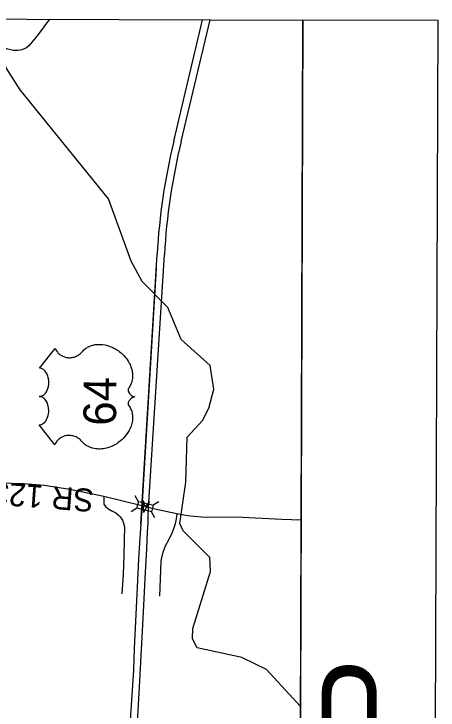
# Model space of a CAD drawing. Extents: x 2364794 to 2387902, y 795230 to 810426.
# Drawn here: x 2366848 to 2367318, y 801786 to 802558 of the extents above; entities that cross this region are included whole.
import ezdxf

# ---------------------------------------------------------------- set-up
doc = ezdxf.new("R2010")
doc.units = 0
for name, color, linetype in [('Default', 7, 'Continuous'), ('Old_Level_10', 7, 'Continuous'), ('Plot Label CELL', 7, 'Continuous'), ('Plot Shape CELL', 7, 'Continuous'), ('User Information Notes CELL', 7, 'Continuous')]:
    doc.layers.add(name, color=color, linetype=linetype)

msp = doc.modelspace()

# ---------------------------------------------------------------- linework, layer by layer
at = {"layer": 'Default'}
for p, q in [((2367318.28, 802550.69), (2367168.28, 802551.22)), ((2367310.68, 800398.89), (2367318.28, 802550.69)), ((2366937.8, 802191.08), (2366938.87, 802191.23)), ((2366938.87, 802191.23), (2366940.97, 802191.39)), ((2366940.97, 802191.39), (2366943.51, 802191.39)), ((2366943.51, 802191.39), (2366945.93, 802191.19)), ((2366945.93, 802191.19), (2366948.74, 802190.72)), ((2366875.76, 802165), (2366893.34, 802186.91)), ((2366893.34, 802186.91), (2366893.54, 802186.39)), ((2366893.54, 802186.39), (2366894.12, 802185.19)), ((2366894.12, 802185.19), (2366894.67, 802184.24)), ((2366894.67, 802184.24), (2366895.73, 802182.73)), ((2366922.49, 802182.24), (2366923.64, 802183.6)), ((2366923.64, 802183.6), (2366924.29, 802184.33)), ((2366924.29, 802184.33), (2366925.13, 802185.17)), ((2366925.13, 802185.17), (2366926.74, 802186.54)), ((2366926.74, 802186.54), (2366927.49, 802187.09)), ((2366927.49, 802187.09), (2366928.34, 802187.65)), ((2366928.34, 802187.65), (2366929.21, 802188.17)), ((2366929.21, 802188.17), (2366930.15, 802188.69)), ((2366930.15, 802188.69), (2366930.96, 802189.1)), ((2366930.96, 802189.1), (2366932.85, 802189.86)), ((2366932.85, 802189.86), (2366934.68, 802190.42)), ((2366934.68, 802190.42), (2366935.64, 802190.68)), ((2366935.64, 802190.68), (2366937.8, 802191.08)), ((2366948.74, 802190.72), (2366950.43, 802190.34)), ((2366950.43, 802190.34), (2366952.39, 802189.75)), ((2366952.39, 802189.75), (2366954.09, 802189.19)), ((2366954.09, 802189.19), (2366956.59, 802188.18)), ((2366956.59, 802188.18), (2366958.4, 802187.28)), ((2366958.4, 802187.28), (2366960.53, 802186.12)), ((2366960.53, 802186.12), (2366961.81, 802185.32)), ((2366961.81, 802185.32), (2366963.18, 802184.4)), ((2366963.18, 802184.4), (2366964.76, 802183.24)), ((2366895.73, 802182.73), (2366896.31, 802182.08)), ((2366896.31, 802182.08), (2366896.92, 802181.43)), ((2366896.92, 802181.43), (2366897.57, 802180.83)), ((2366897.57, 802180.83), (2366898.18, 802180.3)), ((2366898.18, 802180.3), (2366899.06, 802179.66)), ((2366899.06, 802179.66), (2366899.94, 802179.09)), ((2366899.94, 802179.09), (2366900.91, 802178.52)), ((2366900.91, 802178.52), (2366901.75, 802178.11)), ((2366901.75, 802178.11), (2366903.52, 802177.43)), ((2366903.52, 802177.43), (2366904.63, 802177.1)), ((2366904.63, 802177.1), (2366905.58, 802176.89)), ((2366905.58, 802176.89), (2366907.54, 802176.63)), ((2366907.54, 802176.63), (2366908.47, 802176.56)), ((2366908.47, 802176.56), (2366909.39, 802176.55)), ((2366909.39, 802176.55), (2366910.37, 802176.6)), ((2366910.37, 802176.6), (2366911.3, 802176.69)), ((2366911.3, 802176.69), (2366912.28, 802176.86)), ((2366912.28, 802176.86), (2366913.13, 802177.01)), ((2366913.13, 802177.01), (2366914.19, 802177.28)), ((2366914.19, 802177.28), (2366915.41, 802177.66)), ((2366915.41, 802177.66), (2366916.59, 802178.14)), ((2366916.59, 802178.14), (2366918.5, 802179.14)), ((2366918.5, 802179.14), (2366920.46, 802180.42)), ((2366920.46, 802180.42), (2366921.55, 802181.34)), ((2366921.55, 802181.34), (2366922.49, 802182.24)), ((2366964.76, 802183.24), (2366966.45, 802181.88)), ((2366966.45, 802181.88), (2366968.22, 802180.25)), ((2366968.22, 802180.25), (2366969.53, 802178.94)), ((2366969.53, 802178.94), (2366971.05, 802177.22)), ((2366971.05, 802177.22), (2366971.91, 802176.18)), ((2366971.91, 802176.18), (2366973.02, 802174.69)), ((2366973.02, 802174.69), (2366974.36, 802172.67)), ((2366974.36, 802172.67), (2366975.51, 802170.66)), ((2366975.51, 802170.66), (2366976.37, 802168.96)), ((2366976.37, 802168.96), (2366977.02, 802167.45)), ((2366876.41, 802164.97), (2366875.76, 802165)), ((2366877.18, 802164.87), (2366876.41, 802164.97)), ((2366878.06, 802164.65), (2366877.18, 802164.87)), ((2366878.89, 802164.3), (2366878.06, 802164.65)), ((2366879.68, 802163.92), (2366878.89, 802164.3)), ((2366880.45, 802163.38), (2366879.68, 802163.92)), ((2366881.5, 802162.47), (2366880.45, 802163.38)), ((2366882.37, 802161.51), (2366881.5, 802162.47)), ((2366883.02, 802160.7), (2366882.37, 802161.51)), ((2366883.71, 802159.59), (2366883.02, 802160.7)), ((2366977.02, 802167.45), (2366977.75, 802165.5)), ((2366977.75, 802165.5), (2366978.63, 802162.26)), ((2366978.63, 802162.26), (2366978.88, 802161.08)), ((2366978.88, 802161.08), (2366979.08, 802159.67)), ((2366884.41, 802158.23), (2366883.71, 802159.59)), ((2366884.87, 802157.18), (2366884.41, 802158.23)), ((2366885.29, 802155.98), (2366884.87, 802157.18)), ((2366885.64, 802154.66), (2366885.29, 802155.98)), ((2366885.85, 802153.66), (2366885.64, 802154.66)), ((2366886.06, 802152.41), (2366885.85, 802153.66)), ((2366979.14, 802153.68), (2366978.9, 802152.07)), ((2366979.08, 802159.67), (2366979.21, 802158.36)), ((2366979.27, 802155.38), (2366979.14, 802153.68)), ((2366979.21, 802158.36), (2366979.28, 802157.09)), ((2366979.28, 802157.09), (2366979.27, 802155.38)), ((2366885.76, 802144.51), (2366885.95, 802145.65)), ((2366885.95, 802145.65), (2366886.13, 802146.82)), ((2366886.18, 802151.28), (2366886.06, 802152.41)), ((2366886.13, 802146.82), (2366886.22, 802148.01)), ((2366886.24, 802150.18), (2366886.18, 802151.28)), ((2366886.22, 802148.01), (2366886.25, 802148.98)), ((2366886.25, 802148.98), (2366886.24, 802150.18)), ((2366976.59, 802145.45), (2366974.87, 802142.74)), ((2366977.39, 802147.06), (2366976.59, 802145.45)), ((2366978.02, 802148.65), (2366977.39, 802147.06)), ((2366978.54, 802150.4), (2366978.02, 802148.65)), ((2366978.9, 802152.07), (2366978.54, 802150.4)), ((2366882.07, 802136.72), (2366882.52, 802137.27)), ((2366882.52, 802137.27), (2366883.55, 802138.76)), ((2366883.55, 802138.76), (2366884.44, 802140.5)), ((2366884.44, 802140.5), (2366884.82, 802141.36)), ((2366884.82, 802141.36), (2366885.14, 802142.24)), ((2366885.14, 802142.24), (2366885.48, 802143.35)), ((2366885.48, 802143.35), (2366885.76, 802144.51)), ((2366974.33, 802141.52), (2366974.27, 802140.47)), ((2366974.27, 802140.47), (2366974.48, 802139.48)), ((2366974.45, 802141.96), (2366974.33, 802141.52)), ((2366974.87, 802142.74), (2366974.45, 802141.96)), ((2366974.48, 802139.48), (2366974.88, 802138.46)), ((2366974.88, 802138.46), (2366975.2, 802137.85)), ((2366975.2, 802137.85), (2366975.73, 802137.04)), ((2366875.67, 802133.55), (2366876.69, 802133.63)), ((2366876.89, 802133.46), (2366875.67, 802133.55)), ((2366876.69, 802133.63), (2366877.33, 802133.73)), ((2366877.47, 802133.33), (2366876.89, 802133.46)), ((2366877.33, 802133.73), (2366877.95, 802133.9)), ((2366878.79, 802132.86), (2366877.47, 802133.33)), ((2366877.95, 802133.9), (2366878.62, 802134.15)), ((2366878.62, 802134.15), (2366879.55, 802134.62)), ((2366879.42, 802132.52), (2366878.79, 802132.86)), ((2366880.06, 802132.13), (2366879.42, 802132.52)), ((2366879.55, 802134.62), (2366880.33, 802135.13)), ((2366881.22, 802131.2), (2366880.06, 802132.13)), ((2366880.33, 802135.13), (2366881.49, 802136.11)), ((2366882.33, 802130.03), (2366881.22, 802131.2)), ((2366881.49, 802136.11), (2366882.07, 802136.72)), ((2366882.92, 802129.2), (2366882.33, 802130.03)), ((2366976.29, 802130.02), (2366975.61, 802129.19)), ((2366975.73, 802137.04), (2366976.22, 802136.42)), ((2366976.22, 802136.42), (2366976.93, 802135.66)), ((2366976.95, 802130.7), (2366976.29, 802130.02)), ((2366976.93, 802135.66), (2366977.53, 802135.14)), ((2366977.84, 802131.47), (2366976.95, 802130.7)), ((2366977.53, 802135.14), (2366977.99, 802134.74)), ((2366978.53, 802131.95), (2366977.84, 802131.47)), ((2366977.99, 802134.74), (2366979.2, 802133.97)), ((2366979.31, 802132.41), (2366978.53, 802131.95)), ((2366979.2, 802133.97), (2366979.77, 802133.7)), ((2366980.22, 802132.81), (2366979.31, 802132.41)), ((2366979.77, 802133.7), (2366980.51, 802133.41)), ((2366981.59, 802133.16), (2366980.22, 802132.81)), ((2366980.51, 802133.41), (2366981.59, 802133.16)), ((2366883.59, 802128.15), (2366882.92, 802129.2)), ((2366884.29, 802126.83), (2366883.59, 802128.15)), ((2366884.78, 802125.64), (2366884.29, 802126.83)), ((2366885.22, 802124.35), (2366884.78, 802125.64)), ((2366885.51, 802123.2), (2366885.22, 802124.35)), ((2366885.98, 802120.7), (2366885.51, 802123.2)), ((2366974.26, 802126.16), (2366974.21, 802125.52)), ((2366974.21, 802125.52), (2366974.22, 802124.98)), ((2366974.22, 802124.98), (2366974.38, 802124.25)), ((2366974.46, 802126.96), (2366974.26, 802126.16)), ((2366974.38, 802124.25), (2366975.1, 802123.26)), ((2366974.71, 802127.6), (2366974.46, 802126.96)), ((2366975.07, 802128.31), (2366974.71, 802127.6)), ((2366975.61, 802129.19), (2366975.07, 802128.31)), ((2366975.1, 802123.26), (2366975.74, 802122.31)), ((2366975.74, 802122.31), (2366976.37, 802121.28)), ((2366885.46, 802112.31), (2366885.86, 802114.24)), ((2366885.86, 802114.24), (2366886.1, 802116.35)), ((2366886.14, 802118.44), (2366885.98, 802120.7)), ((2366886.1, 802116.35), (2366886.14, 802118.44)), ((2366976.37, 802121.28), (2366977.02, 802120.06)), ((2366977.02, 802120.06), (2366977.43, 802119.17)), ((2366977.43, 802119.17), (2366977.84, 802118.1)), ((2366977.84, 802118.1), (2366978.25, 802116.85)), ((2366978.25, 802116.85), (2366978.6, 802115.5)), ((2366978.6, 802115.5), (2366978.87, 802114.11)), ((2366978.87, 802114.11), (2366979.06, 802112.89)), ((2366881.72, 802105.04), (2366882.8, 802106.34)), ((2366882.8, 802106.34), (2366883.38, 802107.22)), ((2366883.38, 802107.22), (2366884.19, 802108.72)), ((2366884.19, 802108.72), (2366884.91, 802110.42)), ((2366884.91, 802110.42), (2366885.46, 802112.31)), ((2366978.97, 802106.68), (2366978.72, 802105.02)), ((2366979.09, 802108.01), (2366978.97, 802106.68)), ((2366979.06, 802112.89), (2366979.17, 802111.58)), ((2366979.19, 802109.17), (2366979.09, 802108.01)), ((2366979.17, 802111.58), (2366979.2, 802110.4)), ((2366979.2, 802110.4), (2366979.19, 802109.17)), ((2366875.61, 802102.11), (2366876.52, 802102.17)), ((2366893.03, 802080.08), (2366875.61, 802102.11)), ((2366876.52, 802102.17), (2366877.6, 802102.38)), ((2366877.6, 802102.38), (2366878.15, 802102.55)), ((2366878.15, 802102.55), (2366879.22, 802103.05)), ((2366879.22, 802103.05), (2366880.48, 802103.88)), ((2366880.48, 802103.88), (2366881.72, 802105.04)), ((2366976.92, 802099.11), (2366976.04, 802097.11)), ((2366977.53, 802100.7), (2366976.92, 802099.11)), ((2366978.01, 802102.19), (2366977.53, 802100.7)), ((2366978.4, 802103.64), (2366978.01, 802102.19)), ((2366978.72, 802105.02), (2366978.4, 802103.64)), ((2366972.27, 802090.97), (2366970.69, 802089.04)), ((2366974.06, 802093.54), (2366972.27, 802090.97)), ((2366975.32, 802095.73), (2366974.06, 802093.54)), ((2366976.04, 802097.11), (2366975.32, 802095.73)), ((2366895.16, 802083.83), (2366894.52, 802082.94)), ((2366895.89, 802084.76), (2366895.16, 802083.83)), ((2366896.87, 802085.73), (2366895.89, 802084.76)), ((2366897.96, 802086.7), (2366896.87, 802085.73)), ((2366899.3, 802087.63), (2366897.96, 802086.7)), ((2366900.75, 802088.46), (2366899.3, 802087.63)), ((2366901.81, 802088.96), (2366900.75, 802088.46)), ((2366903.27, 802089.5), (2366901.81, 802088.96)), ((2366904.54, 802089.84), (2366903.27, 802089.5)), ((2366906, 802090.12), (2366904.54, 802089.84)), ((2366907.52, 802090.28), (2366906, 802090.12)), ((2366908.82, 802090.32), (2366907.52, 802090.28)), ((2366910.39, 802090.25), (2366908.82, 802090.32)), ((2366911.65, 802090.07), (2366910.39, 802090.25)), ((2366912.98, 802089.81), (2366911.65, 802090.07)), ((2366914.02, 802089.55), (2366912.98, 802089.81)), ((2366915.5, 802089.04), (2366914.02, 802089.55)), ((2366916.46, 802088.64), (2366915.5, 802089.04)), ((2366917.74, 802087.96), (2366916.46, 802088.64)), ((2366918.61, 802087.45), (2366917.74, 802087.96)), ((2366919.58, 802086.81), (2366918.61, 802087.45)), ((2366920.63, 802086.01), (2366919.58, 802086.81)), ((2366921.38, 802085.35), (2366920.63, 802086.01)), ((2366922.62, 802084.07), (2366921.38, 802085.35)), ((2366923.49, 802083), (2366922.62, 802084.07)), ((2366965.87, 802084.32), (2366963.37, 802082.4)), ((2366967.26, 802085.54), (2366965.87, 802084.32)), ((2366969.4, 802087.62), (2366967.26, 802085.54)), ((2366970.69, 802089.04), (2366969.4, 802087.62)), ((2366893.31, 802080.76), (2366893.03, 802080.08)), ((2366893.84, 802081.83), (2366893.31, 802080.76)), ((2366894.52, 802082.94), (2366893.84, 802081.83)), ((2366924.6, 802081.83), (2366923.49, 802083)), ((2366925.82, 802080.7), (2366924.6, 802081.83)), ((2366926.92, 802079.84), (2366925.82, 802080.7)), ((2366928.21, 802078.96), (2366926.92, 802079.84)), ((2366929.42, 802078.27), (2366928.21, 802078.96)), ((2366930.87, 802077.53), (2366929.42, 802078.27)), ((2366932.39, 802076.91), (2366930.87, 802077.53)), ((2366933.76, 802076.44), (2366932.39, 802076.91)), ((2366934.89, 802076.12), (2366933.76, 802076.44)), ((2366936.46, 802075.76), (2366934.89, 802076.12)), ((2366938.29, 802075.46), (2366936.46, 802075.76)), ((2366940.01, 802075.29), (2366938.29, 802075.46)), ((2366945.21, 802075.39), (2366943.27, 802075.26)), ((2366947.04, 802075.63), (2366945.21, 802075.39)), ((2366948.38, 802075.88), (2366947.04, 802075.63)), ((2366950.26, 802076.28), (2366948.38, 802075.88)), ((2366951.34, 802076.57), (2366950.26, 802076.28)), ((2366953.03, 802077.11), (2366951.34, 802076.57)), ((2366954.81, 802077.76), (2366953.03, 802077.11)), ((2366956.76, 802078.58), (2366954.81, 802077.76)), ((2366958.1, 802079.22), (2366956.76, 802078.58)), ((2366960.23, 802080.38), (2366958.1, 802079.22)), ((2366961.56, 802081.18), (2366960.23, 802080.38)), ((2366963.37, 802082.4), (2366961.56, 802081.18)), ((2366941.49, 802075.24), (2366940.01, 802075.29)), ((2366943.27, 802075.26), (2366941.49, 802075.24)), ((2366985.96, 802016.8), (2366982.1, 802023.28)), ((2367008.49, 802016.73), (2367002.01, 802012.87)), ((2366984.11, 802009.49), (2366977.62, 802005.63)), ((2367003.97, 801998.91), (2367000.12, 802005.39))]:
    msp.add_line(p, q, dxfattribs=at)
for points in [[(2365221.07, 800406.27), (2365228.68, 802558.07), (2367168.28, 802551.22), (2367160.68, 800399.42)], [(2365221.07, 800406.27), (2365228.68, 802558.07), (2367168.28, 802551.22), (2367160.68, 800399.42)], [(2367000.12, 802005.39), (2366984.1, 802009.45), (2366986, 802016.93), (2367002.01, 802012.87)], [(2366997.82, 802016.48), (2366991.4, 802004.79), (2366991.11, 802018.12), (2366992.99, 802011.27)]]:
    msp.add_lwpolyline(points, close=True, dxfattribs=at)
msp.add_lwpolyline([(2366996.74, 802010.32), (2366989.3, 802012.18)], dxfattribs=at)
at = {"layer": 'Old_Level_10'}
msp.add_line((2367160.68, 800399.42), (2367168.28, 802551.22), dxfattribs=at)
at = {"layer": 'Plot Label CELL'}
for points in [[(2366886.86, 802552.21), (2366874.6, 802535.38), (2366864.45, 802523.06), (2366861.4, 802520.39), (2366856.4, 802518.39), (2366852.03, 802517.46), (2366846.78, 802517.63), (2366840.65, 802518.89), (2366832.97, 802522.09), (2366827.69, 802524.88), (2366823.06, 802529.42), (2366816.88, 802534.39), (2366811.61, 802536.76), (2366805.02, 802539.09), (2366790.37, 802541.35), (2366785.99, 802542.84), (2366778.98, 802543.42), (2366763.45, 802542.84), (2366670.76, 802542.95)], [(2366947.33, 802022.4), (2366909.47, 802030.47), (2366881.22, 802034.79), (2366858.02, 802036.54), (2366817.35, 802037.88), (2366808.82, 802038.47), (2366785.8, 802042.4), (2366757.54, 802049.56), (2366705.12, 802062.67), (2366691.98, 802067.02), (2366672.34, 802071.47), (2366662.16, 802071.76), (2366650.93, 802070.75)], [(2366947.33, 802022.4), (2366947.15, 802017.27), (2366947.46, 802013.91), (2366949.22, 802011.5), (2366951.62, 802009.4), (2366956.26, 802006.82), (2366960.58, 802004.56), (2366963.3, 802002.31), (2366965.38, 802000.06), (2366967.93, 801996.36), (2366969.2, 801992.83), (2366970.31, 801988.98), (2366969.94, 801974.39), (2366969.55, 801956.92), (2366968.84, 801936.08), (2366967.32, 801914.6)], [(2366989.3, 802012.18), (2366947.33, 802022.4)], [(2367028.27, 802003.37), (2367004.06, 802008.58), (2366990.89, 802011.72)], [(2367028.27, 802003.37), (2367027.63, 801997.83), (2367026.38, 801992.29), (2367025.13, 801987.62), (2367023.27, 801982.45), (2367019.42, 801974.96), (2367015.45, 801967.46), (2367013.09, 801961.43), (2367011.22, 801954.79), (2367010.71, 801950.85), (2367009.78, 801930.9), (2367008.97, 801912.06)], [(2367166.32, 801996.17), (2367145.04, 801996.99), (2367101.16, 801999.27), (2367055.6, 801999.78), (2367040.18, 802000.96), (2367028.27, 802003.37)]]:
    msp.add_lwpolyline(points, dxfattribs=at)
at = {"layer": 'Plot Shape CELL'}
for p, q in [((2367024.89, 802416.87), (2367056.98, 802551.61)), ((2367033, 802416.36), (2367065.2, 802551.58)), ((2366988.49, 801991.89), (2367006.34, 802291.36)), ((2366996.74, 802010.32), (2367014.46, 802290.84))]:
    msp.add_line(p, q, dxfattribs=at)
for points in [[(2367005.42, 802275.78), (2366988.49, 801991.89), (2366987.31, 801976.68), (2366985.86, 801953.08), (2366984.16, 801921.98), (2366980.98, 801853.82), (2366980.2, 801829.83), (2366976.55, 801774.3)], [(2366984.81, 801772.63), (2366986.37, 801804.25), (2366989.34, 801859.33), (2366991.17, 801894.51), (2366993.7, 801938.64), (2366994.97, 801964.47), (2366995.79, 801983.07), (2366996.36, 801993.6), (2366996.65, 802001.77), (2366996.74, 802010.32)]]:
    msp.add_lwpolyline(points, dxfattribs=at)
for centre in [(2367734.05, 802247.98), (2367742.16, 802247.47)]:
    msp.add_arc(centre, 729, 166.60446, 176.58894, dxfattribs=at)
at = {"layer": 'User Information Notes CELL'}
for points in [[(2366952.37, 802352.7), (2366854.55, 802473.77), (2366838.92, 802498.22), (2366831.25, 802520.87), (2366831.58, 802552.41)], [(2367165.59, 801789.69), (2367127.94, 801830.6), (2367100.53, 801844.03), (2367050.97, 801854.48), (2367045.57, 801864.45), (2367046.21, 801876.27), (2367065.75, 801939.27), (2367064.82, 801954.82), (2367035.35, 801984.56), (2367031.47, 801992.65), (2367038.37, 802038.34), (2367039.74, 802088.43), (2367056.99, 802106.85), (2367064.02, 802120.59), (2367069.34, 802141.58), (2367065.48, 802167.94), (2367033.18, 802196.8), (2367018.23, 802232.19), (2366989.88, 802261.04), (2366977.55, 802283.73), (2366952.37, 802352.7)]]:
    msp.add_lwpolyline(points, dxfattribs=at)

# ---------------------------------------------------------------- texts
at = {"layer": 'Default'}
for s, height, p in [('64', 36.308, (2366960.92, 802101.08)), ('VICINITY MAP', 100, (2367286.06, 800950.79))]:
    msp.add_text(s, height=height, rotation=89.79762, dxfattribs=at).set_placement(p)
at = {"layer": 'Plot Label CELL'}
msp.add_text('SR 1233', height=25.362, rotation=175.70042, dxfattribs=at).set_placement((2366937.01, 802030.6))

doc.saveas('drawing.dxf')
